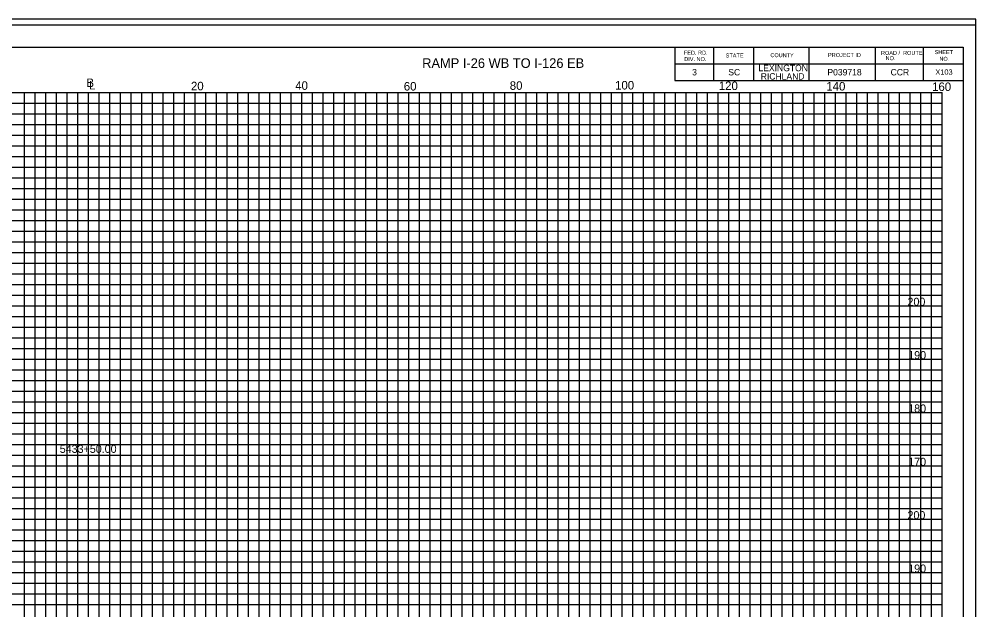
# Model space of a CAD drawing. Extents: x 967 to 1326, y 964 to 3144.
# Drawn here: x 1147 to 1326.3, y 3033 to 3143.7 of the extents above; entities that cross this region are included whole.
import ezdxf

# ---------------------------------------------------------------- set-up
doc = ezdxf.new("R2010")
doc.units = 0
for name, color, linetype in [('Default', 7, 'Continuous'), ('RD_GPK_XS_Cell', 7, 'Continuous'), ('RD_XS_ExGround', 7, 'Continuous'), ('RD_XS_ExPaveRet', 7, 'Continuous'), ('RD_XS_Misc_Line', 7, 'Continuous'), ('RD_XS_TX_Elev_EX', 7, 'Continuous'), ('RD_XS_TX_Station', 7, 'Continuous')]:
    doc.layers.add(name, color=color, linetype=linetype)

msp = doc.modelspace()

# ---------------------------------------------------------------- linework, layer by layer
at = {"layer": 'RD_GPK_XS_Cell'}
for p, q in [((1000, 3130), (1320, 3130)), ((1150, 2960), (1150, 3130)), ((1160, 2960), (1160, 3130)), ((1170, 2960), (1170, 3130)), ((1180, 2960), (1180, 3130)), ((1190, 2960), (1190, 3130)), ((1200, 2960), (1200, 3130)), ((1210, 2960), (1210, 3130)), ((1220, 2960), (1220, 3130)), ((1230, 2960), (1230, 3130)), ((1240, 2960), (1240, 3130)), ((1250, 2960), (1250, 3130)), ((1260, 2960), (1260, 3130)), ((1270, 2960), (1270, 3130)), ((1280, 2960), (1280, 3130)), ((1290, 2960), (1290, 3130)), ((1300, 2960), (1300, 3130)), ((1310, 2960), (1310, 3130)), ((1320, 2960), (1320, 3130)), ((1000, 3120), (1320, 3120)), ((1000, 3110), (1320, 3110)), ((1000, 3100), (1320, 3100)), ((1000, 3090), (1320, 3090)), ((1000, 3080), (1320, 3080)), ((1000, 3070), (1320, 3070)), ((1000, 3060), (1320, 3060)), ((1000, 3050), (1320, 3050)), ((1000, 3040), (1320, 3040))]:
    msp.add_line(p, q, dxfattribs=at)
at = {"layer": 'RD_XS_ExGround'}
for p, q in [((1148, 2960), (1148, 3130)), ((1152, 2960), (1152, 3130)), ((1154, 2960), (1154, 3130)), ((1156, 2960), (1156, 3130)), ((1158, 2960), (1158, 3130)), ((1162, 2960), (1162, 3130)), ((1164, 2960), (1164, 3130)), ((1166, 2960), (1166, 3130)), ((1168, 2960), (1168, 3130)), ((1172, 2960), (1172, 3130)), ((1174, 2960), (1174, 3130)), ((1176, 2960), (1176, 3130)), ((1178, 2960), (1178, 3130)), ((1182, 2960), (1182, 3130)), ((1184, 2960), (1184, 3130)), ((1186, 2960), (1186, 3130)), ((1188, 2960), (1188, 3130)), ((1192, 2960), (1192, 3130)), ((1194, 2960), (1194, 3130)), ((1196, 2960), (1196, 3130)), ((1198, 2960), (1198, 3130)), ((1202, 2960), (1202, 3130)), ((1204, 2960), (1204, 3130)), ((1206, 2960), (1206, 3130)), ((1208, 2960), (1208, 3130)), ((1212, 2960), (1212, 3130)), ((1214, 2960), (1214, 3130)), ((1216, 2960), (1216, 3130)), ((1218, 2960), (1218, 3130)), ((1222, 2960), (1222, 3130)), ((1224, 2960), (1224, 3130)), ((1226, 2960), (1226, 3130)), ((1228, 2960), (1228, 3130)), ((1232, 2960), (1232, 3130)), ((1234, 2960), (1234, 3130)), ((1236, 2960), (1236, 3130)), ((1238, 2960), (1238, 3130)), ((1242, 2960), (1242, 3130)), ((1244, 2960), (1244, 3130)), ((1246, 2960), (1246, 3130)), ((1248, 2960), (1248, 3130)), ((1252, 2960), (1252, 3130)), ((1254, 2960), (1254, 3130)), ((1256, 2960), (1256, 3130)), ((1258, 2960), (1258, 3130)), ((1262, 2960), (1262, 3130)), ((1264, 2960), (1264, 3130)), ((1266, 2960), (1266, 3130)), ((1268, 2960), (1268, 3130)), ((1272, 2960), (1272, 3130)), ((1274, 2960), (1274, 3130)), ((1276, 2960), (1276, 3130)), ((1278, 2960), (1278, 3130)), ((1282, 2960), (1282, 3130)), ((1284, 2960), (1284, 3130)), ((1286, 2960), (1286, 3130)), ((1288, 2960), (1288, 3130)), ((1292, 2960), (1292, 3130)), ((1294, 2960), (1294, 3130)), ((1296, 2960), (1296, 3130)), ((1298, 2960), (1298, 3130)), ((1302, 2960), (1302, 3130)), ((1304, 2960), (1304, 3130)), ((1306, 2960), (1306, 3130)), ((1308, 2960), (1308, 3130)), ((1312, 2960), (1312, 3130)), ((1314, 2960), (1314, 3130)), ((1316, 2960), (1316, 3130)), ((1318, 2960), (1318, 3130)), ((1000, 3128), (1320, 3128)), ((1000, 3126), (1320, 3126)), ((1000, 3124), (1320, 3124)), ((1000, 3122), (1320, 3122)), ((1000, 3118), (1320, 3118)), ((1000, 3116), (1320, 3116)), ((1000, 3114), (1320, 3114)), ((1000, 3112), (1320, 3112)), ((1000, 3108), (1320, 3108)), ((1000, 3106), (1320, 3106)), ((1000, 3104), (1320, 3104)), ((1000, 3102), (1320, 3102)), ((1000, 3098), (1320, 3098)), ((1000, 3096), (1320, 3096)), ((1000, 3094), (1320, 3094)), ((1000, 3092), (1320, 3092)), ((1000, 3088), (1320, 3088)), ((1000, 3086), (1320, 3086)), ((1000, 3084), (1320, 3084)), ((1000, 3082), (1320, 3082)), ((1000, 3078), (1320, 3078)), ((1000, 3076), (1320, 3076)), ((1000, 3074), (1320, 3074)), ((1000, 3072), (1320, 3072)), ((1000, 3068), (1320, 3068)), ((1000, 3066), (1320, 3066)), ((1000, 3064), (1320, 3064)), ((1000, 3062), (1320, 3062)), ((1000, 3058), (1320, 3058)), ((1000, 3056), (1320, 3056)), ((1000, 3054), (1320, 3054)), ((1000, 3052), (1320, 3052)), ((1000, 3048), (1320, 3048)), ((1000, 3046), (1320, 3046)), ((1000, 3044), (1320, 3044)), ((1000, 3042), (1320, 3042)), ((1000, 3038), (1320, 3038)), ((1000, 3036), (1320, 3036)), ((1000, 3034), (1320, 3034))]:
    msp.add_line(p, q, dxfattribs=at)
at = {"layer": 'RD_XS_ExPaveRet'}
for points in [[(967.41, 2923.72), (1326.28, 2923.72), (1326.28, 3143.72), (967.41, 3143.72)], [(988.52, 2924.84), (1326.28, 2924.84), (1326.28, 3142.6), (988.52, 3142.6)]]:
    msp.add_lwpolyline(points, close=True, dxfattribs=at)
at = {"layer": 'RD_XS_TX_Elev_EX'}
for p, q in [((996.11, 3138.46), (1323.89, 3138.46)), ((1269.89, 3138.46), (1269.89, 3132.21)), ((1277.14, 3138.46), (1277.14, 3132.21)), ((1284.64, 3138.46), (1284.64, 3132.21)), ((1295, 3138.46), (1295, 3132.21)), ((1307.43, 3138.46), (1307.43, 3132.21)), ((1316.39, 3138.46), (1316.39, 3132.21)), ((1323.89, 3138.46), (1323.89, 2928.98)), ((1269.89, 3135.33), (1323.89, 3135.33)), ((1269.89, 3132.21), (1323.89, 3132.21))]:
    msp.add_line(p, q, dxfattribs=at)
at = {"layer": 'RD_XS_TX_Station'}
msp.add_lwpolyline([(967.41, 2923.72), (1326.28, 2923.72), (1326.28, 3143.72), (967.41, 3143.72)], close=True, dxfattribs=at)

# ---------------------------------------------------------------- texts
at = {"layer": 'Default'}
for s, height, p in [('X103', 1, (1318.7, 3133.3)), ('200', 1.5, (1313.47, 3090)), ('190', 1.5, (1313.61, 3080)), ('180', 1.5, (1313.61, 3070)), ('5433+50.00', 1.5, (1154.61, 3062.42)), ('170', 1.5, (1313.61, 3060)), ('200', 1.5, (1313.47, 3050)), ('190', 1.5, (1313.61, 3040))]:
    msp.add_text(s, height=height, dxfattribs=at).set_placement(p)
at = {"layer": 'RD_XS_Misc_Line'}
for s, height, p in [('FED. RD.', 0.75, (1271.58, 3137.05)), ('ROAD /  ROUTE', 0.75, (1308.51, 3137.01)), ('SHEET', 0.75, (1318.56, 3137.16)), ('DIV. NO.', 0.75, (1271.64, 3135.86)), ('STATE', 0.75, (1279.41, 3136.53)), ('COUNTY', 0.75, (1287.78, 3136.59)), ('PROJECT ID', 0.75, (1298.58, 3136.63)), ('   NO.', 0.75, (1308.51, 3136.03)), ('NO.', 0.75, (1319.45, 3135.91)), ('3', 1.2, (1273.12, 3133.17)), ('SC', 1.2, (1279.89, 3133.17)), ('LEXINGTON', 1.2, (1285.54, 3133.96)), ('P039718', 1.2, (1298.46, 3133.17)), ('CCR', 1.2, (1310.31, 3133.17)), ('B', 1.6, (1159.61, 3130.99)), ('L', 1.6, (1160.12, 3130.54)), ('100', 1.6, (1258.67, 3130.53)), ('RICHLAND', 1.2, (1285.97, 3132.39)), ('20', 1.6, (1179.2, 3130.38)), ('40', 1.6, (1198.74, 3130.47)), ('60', 1.6, (1219.08, 3130.33)), ('80', 1.6, (1238.94, 3130.47)), ('120', 1.6, (1278.11, 3130.43)), ('140', 1.6, (1298.26, 3130.34)), ('160', 1.6, (1318.08, 3130.25))]:
    msp.add_text(s, height=height, dxfattribs=at).set_placement(p)
msp.add_text('RAMP I-26 WB TO I-126 EB', height=1.8, rotation=0, dxfattribs=at).set_placement((1222.53, 3134.58))

doc.saveas('drawing.dxf')
